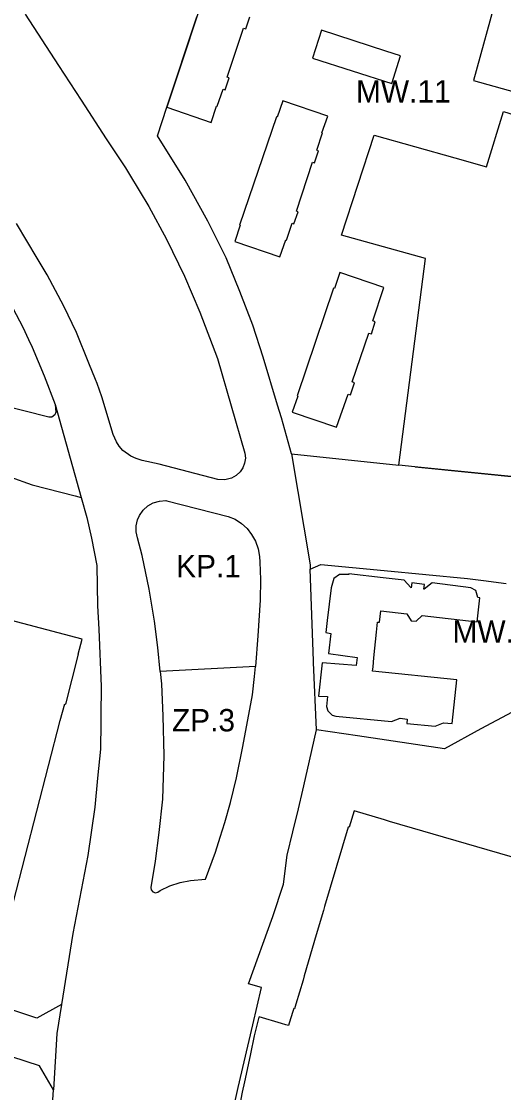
# Model space of a CAD drawing. Extents: x 7424052 to 7425705, y 5546602 to 5547569.
# Drawn here: x 7425056.7 to 7425164.6, y 5546961.1 to 5547200.9 of the extents above; entities that cross this region are included whole.
import ezdxf

# ---------------------------------------------------------------- set-up
doc = ezdxf.new("R2010")
doc.units = 0
for name, color, linetype in [('linie rozgraniczające', 7, 'Continuous'), ('nieprzekraczalne linie zabudowy', 7, 'Continuous'), ('obowiazujace linie zabudowy', 7, 'Continuous'), ('przeznaczenia terenów', 7, 'Continuous')]:
    doc.layers.add(name, color=color, linetype=linetype)

msp = doc.modelspace()

# ---------------------------------------------------------------- linework, layer by layer
at = {"layer": 'linie rozgraniczające'}
for p, q in [((7425057.52, 5547202.6), (7425064.98, 5547191.05)), ((7425089.21, 5547181.77), (7425095.9, 5547201.94)), ((7425064.98, 5547191.05), (7425070.06, 5547183.34)), ((7425070.06, 5547183.34), (7425075.67, 5547174.69)), ((7425087.14, 5547175.35), (7425089.21, 5547181.77)), ((7425160.74, 5547168.37), (7425164.56, 5547180.78)), ((7425164.56, 5547180.78), (7425176.17, 5547177.02)), ((7425075.67, 5547174.69), (7425079.96, 5547168.14)), ((7425093.35, 5547165.38), (7425087.14, 5547175.35)), ((7425128.29, 5547153.07), (7425135.64, 5547175.5)), ((7425135.64, 5547175.5), (7425153.67, 5547170.38)), ((7425153.67, 5547170.38), (7425160.74, 5547168.37)), ((7425079.96, 5547168.14), (7425080.88, 5547166.68)), ((7425080.88, 5547166.68), (7425085.17, 5547159.53)), ((7425098.43, 5547156.26), (7425093.35, 5547165.38)), ((7425085.17, 5547159.53), (7425089.18, 5547152.21)), ((7425060.19, 5547147.96), (7425055.55, 5547155.68)), ((7425102.49, 5547148.02), (7425098.43, 5547156.26)), ((7425147.13, 5547147.85), (7425128.29, 5547153.07)), ((7425089.18, 5547152.21), (7425093.15, 5547143.91)), ((7425062.43, 5547144.21), (7425060.19, 5547147.96)), ((7425105.52, 5547140.51), (7425102.49, 5547148.02)), ((7425141.16, 5547101.58), (7425147.13, 5547147.85)), ((7425066.16, 5547137.18), (7425062.43, 5547144.21)), ((7425093.15, 5547143.91), (7425096.63, 5547135.86)), ((7425108.48, 5547132.92), (7425105.52, 5547140.51)), ((7425054.75, 5547136.73), (7425057.01, 5547132.49)), ((7425069.04, 5547131.3), (7425066.16, 5547137.18)), ((7425096.63, 5547135.86), (7425100.56, 5547125.5)), ((7425057.01, 5547132.49), (7425058.3, 5547129.7)), ((7425071.77, 5547124.43), (7425069.04, 5547131.3)), ((7425110.74, 5547125.78), (7425108.48, 5547132.92)), ((7425058.3, 5547129.7), (7425059.07, 5547128.04)), ((7425059.07, 5547128.04), (7425061.76, 5547121.58)), ((7425073.29, 5547120.75), (7425071.77, 5547124.43)), ((7425100.56, 5547125.5), (7425106.71, 5547104.25)), ((7425114, 5547115.06), (7425110.74, 5547125.78)), ((7425061.76, 5547121.58), (7425064.22, 5547115.18)), ((7425073.63, 5547119.86), (7425073.29, 5547120.75)), ((7425074.68, 5547116.93), (7425073.63, 5547119.86)), ((7425062.82, 5547112.32), (7425045.42, 5547116.78)), ((7425077.21, 5547108.5), (7425074.68, 5547116.93)), ((7425064.22, 5547115.18), (7425070.04, 5547094.37)), ((7425064.22, 5547115.18), (7425064.35, 5547113.5)), ((7425114.9, 5547112.19), (7425114, 5547115.06)), ((7425063.48, 5547112.36), (7425062.82, 5547112.32)), ((7425064.14, 5547112.89), (7425063.48, 5547112.36)), ((7425064.35, 5547113.5), (7425064.14, 5547112.89)), ((7425064.14, 5547112.89), (7425064.14, 5547112.89)), ((7425117.08, 5547104.14), (7425114.9, 5547112.19)), ((7425077.95, 5547106.8), (7425077.21, 5547108.5)), ((7425078.57, 5547105.85), (7425077.95, 5547106.8)), ((7425079.41, 5547104.91), (7425078.57, 5547105.85)), ((7425081.18, 5547103.59), (7425079.41, 5547104.91)), ((7425082.33, 5547103.06), (7425081.18, 5547103.59)), ((7425083.68, 5547102.68), (7425082.33, 5547103.06)), ((7425087.53, 5547101.84), (7425083.68, 5547102.68)), ((7425106.8, 5547103.19), (7425106.63, 5547102.05)), ((7425106.71, 5547104.25), (7425106.8, 5547103.19)), ((7425117.08, 5547104.14), (7425141.16, 5547101.58)), ((7425117.08, 5547104.14), (7425121.26, 5547079.31)), ((7425100.64, 5547098.41), (7425087.53, 5547101.84)), ((7425105.61, 5547100.08), (7425104.77, 5547099.29)), ((7425106.23, 5547101), (7425105.61, 5547100.08)), ((7425106.63, 5547102.05), (7425106.23, 5547101)), ((7425146.14, 5547101.08), (7425141.16, 5547101.58)), ((7425171.61, 5547098.54), (7425146.14, 5547101.08)), ((7425054.11, 5547099), (7425059.05, 5547097.2)), ((7425102.18, 5547098.3), (7425100.64, 5547098.41)), ((7425103.71, 5547098.68), (7425102.18, 5547098.3)), ((7425104.77, 5547099.29), (7425103.71, 5547098.68)), ((7425059.05, 5547097.2), (7425068.74, 5547094.7)), ((7425068.74, 5547094.7), (7425070.04, 5547094.37)), ((7425070.04, 5547094.37), (7425071.29, 5547089.88)), ((7425084.95, 5547092.47), (7425086.18, 5547093.17)), ((7425086.18, 5547093.17), (7425087.55, 5547093.57)), ((7425087.55, 5547093.57), (7425088.96, 5547093.66)), ((7425088.96, 5547093.66), (7425089.2, 5547093.64)), ((7425089.2, 5547093.64), (7425102.91, 5547090.1)), ((7425083.08, 5547090.35), (7425083.89, 5547091.52)), ((7425083.89, 5547091.52), (7425084.95, 5547092.47)), ((7425071.29, 5547089.88), (7425072.4, 5547085.27)), ((7425082.33, 5547088.03), (7425082.63, 5547089.36)), ((7425082.35, 5547086.66), (7425082.33, 5547088.03)), ((7425082.63, 5547089.36), (7425083.08, 5547090.35)), ((7425102.91, 5547090.1), (7425104.49, 5547089.48)), ((7425104.49, 5547089.48), (7425105.93, 5547088.57)), ((7425105.93, 5547088.57), (7425107.17, 5547087.41)), ((7425082.69, 5547085.33), (7425082.35, 5547086.66)), ((7425107.17, 5547087.41), (7425108.13, 5547086.11)), ((7425108.13, 5547086.11), (7425109.04, 5547084.56)), ((7425072.4, 5547085.27), (7425073.54, 5547079.15)), ((7425083.69, 5547081.39), (7425082.69, 5547085.33)), ((7425109.04, 5547084.56), (7425109.66, 5547082.88)), ((7425085.25, 5547073.83), (7425083.69, 5547081.39)), ((7425109.66, 5547082.88), (7425109.98, 5547081.12)), ((7425109.98, 5547081.12), (7425110.01, 5547079.86)), ((7425073.54, 5547079.15), (7425073.68, 5547070.13)), ((7425110.01, 5547079.86), (7425110.17, 5547076.02)), ((7425121.26, 5547079.31), (7425121.3, 5547078.3)), ((7425121.3, 5547078.3), (7425123.7, 5547079.38)), ((7425123.7, 5547079.38), (7425137.82, 5547078.02)), ((7425110.17, 5547076.02), (7425110.09, 5547071.36)), ((7425122.03, 5547057.79), (7425121.3, 5547078.3)), ((7425137.82, 5547078.02), (7425156.53, 5547076.25)), ((7425156.53, 5547076.25), (7425160.05, 5547075.79)), ((7425086.44, 5547066.7), (7425085.25, 5547073.83)), ((7425160.05, 5547075.79), (7425165.13, 5547075.14)), ((7425110.09, 5547071.36), (7425109.56, 5547063.36)), ((7425073.68, 5547070.13), (7425074.01, 5547064.86)), ((7425087.18, 5547060.77), (7425086.44, 5547066.7)), ((7425074.01, 5547064.86), (7425074.52, 5547052.08)), ((7425109.56, 5547063.36), (7425109.04, 5547056.54)), ((7425087.73, 5547055.42), (7425087.18, 5547060.77)), ((7425122.05, 5547057.39), (7425122.03, 5547057.79)), ((7425122.74, 5547042.32), (7425122.05, 5547057.39)), ((7425109.04, 5547056.54), (7425087.73, 5547055.42)), ((7425087.73, 5547055.42), (7425088.01, 5547052.68)), ((7425108.87, 5547054.31), (7425109.04, 5547056.54)), ((7425074.52, 5547052.08), (7425074.48, 5547045.56)), ((7425088.01, 5547052.68), (7425088.34, 5547045.37)), ((7425108.37, 5547050.15), (7425108.87, 5547054.31)), ((7425106.26, 5547038.65), (7425108.37, 5547050.15)), ((7425170.57, 5547048.5), (7425159.48, 5547042.54)), ((7425074.48, 5547045.56), (7425074.47, 5547043.93)), ((7425088.34, 5547045.37), (7425088.56, 5547036.62)), ((7425074.47, 5547043.93), (7425074.36, 5547038.03)), ((7425159.48, 5547042.54), (7425151.37, 5547038.08)), ((7425120.61, 5547033.07), (7425122.74, 5547042.32)), ((7425131.85, 5547040.97), (7425122.74, 5547042.32)), ((7425151.37, 5547038.08), (7425131.85, 5547040.97)), ((7425074.36, 5547038.03), (7425073.72, 5547031.52)), ((7425104.83, 5547031.63), (7425106.26, 5547038.65)), ((7425088.56, 5547036.62), (7425088.25, 5547026.82)), ((7425119.64, 5547028.87), (7425120.61, 5547033.07)), ((7425073.72, 5547031.52), (7425073.09, 5547025)), ((7425103.49, 5547026.11), (7425104.83, 5547031.63)), ((7425118.68, 5547024.68), (7425119.64, 5547028.87)), ((7425088.25, 5547026.82), (7425087.4, 5547019.33)), ((7425102.17, 5547021.61), (7425103.49, 5547026.11)), ((7425073.09, 5547025), (7425071.53, 5547014.18)), ((7425117.41, 5547019.49), (7425118.68, 5547024.68)), ((7425101.13, 5547018.28), (7425102.17, 5547021.61)), ((7425087.4, 5547019.33), (7425086.63, 5547012.92)), ((7425116.14, 5547014.3), (7425117.41, 5547019.49)), ((7425100.09, 5547014.95), (7425101.13, 5547018.28)), ((7425071.53, 5547014.18), (7425068.2, 5546996.76)), ((7425097.89, 5547008.92), (7425100.09, 5547014.95)), ((7425115.3, 5547007.82), (7425116.14, 5547014.3)), ((7425060.14, 5546977.83), (7424953.05, 5547012.95)), ((7425086.63, 5547012.92), (7425085.62, 5547007.08)), ((7425094.54, 5547008.61), (7425097.89, 5547008.92)), ((7425085.62, 5547007.08), (7425085.72, 5547006.5)), ((7425085.72, 5547006.5), (7425086.1, 5547006.06)), ((7425087.73, 5547006.38), (7425089.89, 5547007.42)), ((7425089.89, 5547007.42), (7425092.18, 5547008.17)), ((7425092.18, 5547008.17), (7425094.54, 5547008.61)), ((7425112.91, 5547000.56), (7425115.3, 5547007.82)), ((7425086.1, 5547006.06), (7425086.65, 5547005.87)), ((7425086.65, 5547005.87), (7425087.18, 5547005.98)), ((7425087.18, 5547005.98), (7425087.73, 5547006.38)), ((7425107.48, 5546985.46), (7425112.91, 5547000.56)), ((7425068.2, 5546996.76), (7425065.64, 5546980.89)), ((7425110.38, 5546984.64), (7425107.48, 5546985.46)), ((7425108.45, 5546976.32), (7425110.38, 5546984.64)), ((7425065.64, 5546980.89), (7425060.14, 5546977.83)), ((7425065.64, 5546980.89), (7425064.58, 5546974.39)), ((7425106.52, 5546968), (7425108.45, 5546976.32)), ((7425064.58, 5546974.39), (7425063.89, 5546961.78)), ((7425105.21, 5546962.26), (7425106.52, 5546968)), ((7425103.9, 5546956.52), (7425105.21, 5546962.26))]:
    msp.add_line(p, q, dxfattribs=at)
msp.add_lwpolyline([(7425057.52, 5546865.73), (7425063.89, 5546961.78), (7425060.73, 5546967.11), (7425025.83, 5546978.44), (7424970.91, 5546996.51), (7424916, 5547014.59), (7424869.23, 5547029.94), (7424833.88, 5547041.92)], dxfattribs=at)
at = {"layer": 'nieprzekraczalne linie zabudowy'}
for p, q in [((7425123.85, 5547198.96), (7425121.84, 5547192.74)), ((7425138.26, 5547194.27), (7425123.85, 5547198.96)), ((7425141.5, 5547193.22), (7425138.26, 5547194.27)), ((7425121.84, 5547192.74), (7425139.55, 5547187.06)), ((7425139.55, 5547187.06), (7425141.5, 5547193.22)), ((7425144.77, 5547101.25), (7425144.77, 5547101.25)), ((7425144.77, 5547101.25), (7425171.85, 5547098.52))]:
    msp.add_line(p, q, dxfattribs=at)
at = {"layer": 'obowiazujace linie zabudowy'}
for p, q in [((7425070.24, 5547062.67), (7425053.06, 5547067.21)), ((7425069.36, 5547059.26), (7425070.24, 5547062.67)), ((7425066.64, 5547048.09), (7425069.49, 5547059.26)), ((7425069.49, 5547059.26), (7425069.36, 5547059.26)), ((7425065.32, 5547044.44), (7425066.39, 5547048.19)), ((7425066.39, 5547048.19), (7425066.64, 5547048.09)), ((7425052.32, 5546993.68), (7425065.32, 5547044.44))]:
    msp.add_line(p, q, dxfattribs=at)
for points in [[(7425114.32, 5547223.4), (7425118.4, 5547222.43), (7425117.45, 5547219.63), (7425123.63, 5547217.39), (7425126.13, 5547216.6), (7425125.89, 5547215.03), (7425131.54, 5547213.46), (7425133.04, 5547213.04), (7425142.47, 5547210.57), (7425143.16, 5547213.14), (7425156.22, 5547209.54), (7425156.08, 5547209.04), (7425163.15, 5547207.08), (7425157.81, 5547187.71), (7425173.37, 5547183.41)], [(7425099.58, 5547213.04), (7425089.21, 5547181.77), (7425099.13, 5547178.33), (7425100.37, 5547182), (7425100.48, 5547181.96), (7425101.86, 5547185.75), (7425102.28, 5547185.6), (7425103.19, 5547188.32), (7425102.7, 5547188.49), (7425106.38, 5547199.45), (7425106.9, 5547199.27), (7425107.81, 5547202)], [(7425115.18, 5547183.15), (7425113.92, 5547179.5), (7425113.78, 5547179.55), (7425105.5, 5547155.34), (7425105.63, 5547155.3), (7425104.43, 5547151.66), (7425114.54, 5547148.25), (7425115.83, 5547152.02), (7425115.97, 5547151.97), (7425117.26, 5547155.77), (7425117.64, 5547155.64), (7425118.57, 5547158.35), (7425118.23, 5547158.48), (7425121.84, 5547169.4), (7425122.23, 5547169.25), (7425123.16, 5547171.97), (7425122.82, 5547172.09), (7425124.05, 5547175.99), (7425123.93, 5547176.03), (7425125.22, 5547179.74), (7425115.18, 5547183.15)], [(7425127.91, 5547144.73), (7425126.71, 5547141.16), (7425126.52, 5547141.22), (7425118.36, 5547117.12), (7425118.52, 5547117.07), (7425117.29, 5547113.48), (7425127.15, 5547110.12), (7425129.8, 5547117.51), (7425130.32, 5547117.34), (7425131.22, 5547120.06), (7425130.72, 5547120.22), (7425134.45, 5547131.17), (7425134.98, 5547131.01), (7425135.87, 5547133.7), (7425135.33, 5547133.88), (7425137.79, 5547141.4), (7425127.91, 5547144.73)], [(7425129.98, 5547077.29), (7425129.96, 5547077.09), (7425127.84, 5547077.12), (7425126.59, 5547076.23), (7425125.99, 5547074.17), (7425125.1, 5547066.82), (7425124.78, 5547064.16), (7425125.94, 5547063.89), (7425125.4, 5547059.42), (7425131.82, 5547058.52), (7425131.55, 5547056.78), (7425123.97, 5547057.37), (7425123.13, 5547049.88), (7425125.15, 5547049.83), (7425124.93, 5547047.55), (7425125.24, 5547046.6), (7425126.22, 5547045.66), (7425127.03, 5547045.38), (7425139.46, 5547044.18), (7425141.4, 5547044.98), (7425142.98, 5547044.76), (7425142.89, 5547043.78), (7425149.25, 5547043.14), (7425151.15, 5547043.94), (7425153.08, 5547043.75), (7425154.1, 5547053.53), (7425135.22, 5547055.48), (7425135.37, 5547056.48), (7425135.55, 5547058.48), (7425136.1, 5547064.21), (7425136.38, 5547066.47), (7425136.81, 5547066.43), (7425137.13, 5547069), (7425142.89, 5547068.29), (7425143.88, 5547066.78), (7425144.98, 5547066.65), (7425146.37, 5547067.91), (7425158.66, 5547066.51), (7425159.29, 5547071.91), (7425158.83, 5547071.99), (7425158.36, 5547073.51), (7425157.25, 5547074.16), (7425148.56, 5547075.25), (7425146.8, 5547073.82), (7425146.71, 5547073.83), (7425146.84, 5547074.9), (7425144.02, 5547075.26), (7425143.89, 5547074.17), (7425143.81, 5547074.18), (7425142.33, 5547075.83), (7425137.62, 5547076.39), (7425129.98, 5547077.29)], [(7425185.56, 5547008.35), (7425139.05, 5547021.86), (7425137.9, 5547022.19), (7425131.12, 5547024.2), (7425130.02, 5547020.53), (7425129.76, 5547020.57), (7425124.49, 5547002.76), (7425124.29, 5547001.88), (7425122.67, 5546996.47), (7425119.93, 5546987.25), (7425119.69, 5546986.33), (7425118.08, 5546980.95), (7425117.81, 5546979.92), (7425117.61, 5546979.99), (7425117.39, 5546979.25), (7425116.62, 5546976.71), (7425116.44, 5546976.15), (7425115.85, 5546976.33), (7425114.85, 5546976.63), (7425109.91, 5546978.08), (7425109.88, 5546977.99), (7425109.8, 5546978.01), (7425108.78, 5546973.86), (7425107.95, 5546969.81), (7425107.17, 5546966.27), (7425106.61, 5546963.54), (7425106.1, 5546961.19), (7425105.56, 5546958.44)]]:
    msp.add_lwpolyline(points, dxfattribs=at)

# ---------------------------------------------------------------- texts
at = {"layer": 'przeznaczenia terenów'}
for s, p in [('MW.11', (7425131.55, 5547182.78)), ('KP.1', (7425091.3, 5547076.5)), ('MW.17', (7425153.14, 5547061.83)), ('ZP.3', (7425090.36, 5547042))]:
    msp.add_text(s, height=5, dxfattribs=at).set_placement(p)

doc.saveas('drawing.dxf')
